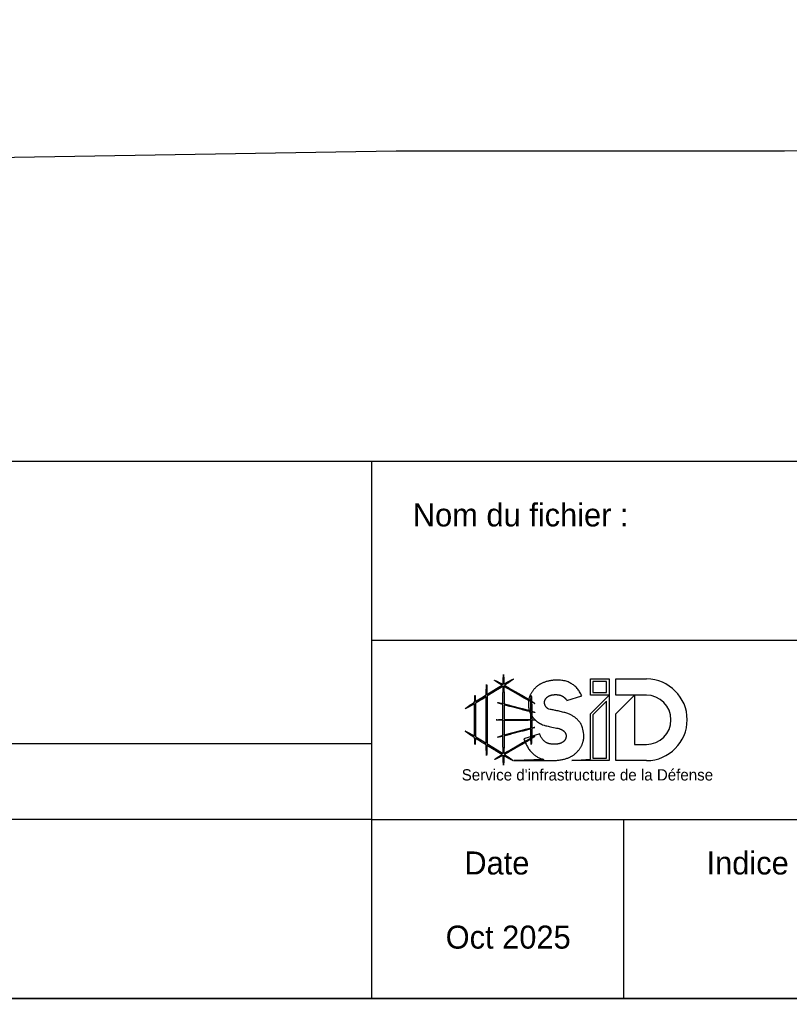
# Model space of a CAD drawing. Extents: x 37864 to 38032, y 453991 to 454052.
# Drawn here: x 38013.02 to 38023.04, y 453990.82 to 454003.57 of the extents above; entities that cross this region are included whole.
import ezdxf

# ---------------------------------------------------------------- set-up
doc = ezdxf.new("R2010")
doc.units = 0
doc.layers.add('PS_Dim', color=7, linetype='Continuous')

msp = doc.modelspace()

# ---------------------------------------------------------------- linework, layer by layer
at = {"layer": 'DEFPOINTS'}
for p, q in [((38017.598, 453997.816), (38017.598, 453990.816)), ((38017.598, 453995.483), (38027.447, 453995.483)), ((38019.104, 453994.778), (38019.226, 453994.853)), ((38019.54, 453994.758), (38019.378, 453994.851)), ((38019.386, 453994.865), (38019.548, 453994.772)), ((38019.033, 453994.734), (38019.094, 453994.772)), ((38019.093, 453994.748), (38019.044, 453994.717)), ((38019.237, 453994.836), (38019.104, 453994.754)), ((38019.312, 453994.657), (38019.312, 453994.716)), ((38019.326, 453994.716), (38019.326, 453994.654)), ((38020.144, 453994.7), (38020.339, 453994.76)), ((38019.092, 453994.303), (38019.092, 453994.588)), ((38019.106, 453994.588), (38019.106, 453994.303)), ((38019.312, 453994.451), (38019.312, 453994.647)), ((38019.326, 453994.643), (38019.326, 453994.451)), ((38019.556, 453994.581), (38019.407, 453994.62)), ((38019.41, 453994.633), (38019.56, 453994.594)), ((38018.941, 453994.347), (38018.941, 453994.544)), ((38018.955, 453994.544), (38018.955, 453994.347)), ((38019.673, 453994.45), (38019.673, 453994.544)), ((38019.687, 453994.544), (38019.687, 453994.449)), ((38019.312, 453994.244), (38019.312, 453994.44)), ((38019.326, 453994.44), (38019.326, 453994.248)), ((38019.398, 453994.452), (38019.552, 453994.452)), ((38019.552, 453994.439), (38019.398, 453994.439)), ((38019.673, 453994.347), (38019.673, 453994.441)), ((38019.687, 453994.442), (38019.687, 453994.347)), ((38019.312, 453994.175), (38019.312, 453994.234)), ((38019.326, 453994.237), (38019.326, 453994.175)), ((38019.407, 453994.271), (38019.556, 453994.31)), ((38019.56, 453994.297), (38019.41, 453994.258)), ((38019.094, 453994.119), (38019.033, 453994.157)), ((38019.044, 453994.174), (38019.093, 453994.143)), ((38019.104, 453994.137), (38019.237, 453994.055)), ((38019.226, 453994.038), (38019.104, 453994.113)), ((38019.378, 453994.04), (38019.54, 453994.133)), ((38019.548, 453994.119), (38019.386, 453994.026)), ((38019.842, 453993.93), (38019.457, 453993.916)), ((38019.457, 453993.916), (38019.968, 453993.916)), ((38017.598, 453993.149), (38032.431, 453993.149)), ((38020.881, 453993.149), (38020.881, 453990.816))]:
    msp.add_line(p, q, dxfattribs=at)
for points in [[(37950.431, 453990.816), (38032.431, 453990.816), (38032.431, 454048.216), (37950.431, 454048.216)], [(37992.431, 453997.816), (38032.431, 453997.816), (38032.431, 453990.816), (37992.431, 453990.816)], [(38020.451, 453994.979), (38020.694, 453994.979), (38020.694, 453994.768), (38020.451, 453994.768)], [(38020.484, 453994.801), (38020.662, 453994.801), (38020.662, 453994.946), (38020.484, 453994.946)], [(38020.694, 453993.916), (38020.451, 453993.916), (38020.209, 453993.916), (38020.451, 453993.936), (38020.451, 453994.525), (38020.694, 453994.768)], [(38020.662, 453994.689), (38020.484, 453994.511), (38020.484, 453993.948), (38020.662, 453993.948)], [(38002.944, 453994.139), (38017.598, 453994.139), (38017.598, 453993.149), (38002.944, 453993.149)]]:
    msp.add_lwpolyline(points, close=True, dxfattribs=at)
for points in [[(38021.179, 453994.768), (38020.783, 453994.768), (38020.783, 453994.979), (38021.183, 453994.979)], [(38021.183, 453993.916), (38020.783, 453993.916), (38020.783, 453994.525), (38021.026, 453994.768), (38021.026, 453994.126), (38021.179, 453994.126)], [(38019.796, 453994.247), (38019.79, 453994.264), (38019.585, 453994.201)]]:
    msp.add_lwpolyline(points, dxfattribs=at)
for radius, start, end in [(0.532, 270.4248, 89.5752), (0.321, 270, 90)]:
    msp.add_arc((38021.179, 453994.447), radius, start, end, dxfattribs=at)
for points, degree in [([(38019.314, 453994.906), (38019.315, 453994.961), (38019.317, 453995.008), (38019.319, 453995.036)], 2), ([(38019.319, 453995.036), (38019.321, 453995.009), (38019.323, 453994.964), (38019.324, 453994.912)], 2), ([(38019.324, 453994.912), (38019.375, 453994.941), (38019.422, 453994.967), (38019.448, 453994.978)], 2), ([(38019.448, 453994.978), (38019.427, 453994.96), (38019.381, 453994.929), (38019.331, 453994.896)], 2), ([(38019.094, 453994.772), (38019.095, 453994.829), (38019.096, 453994.879), (38019.099, 453994.908)], 2), ([(38019.099, 453994.908), (38019.101, 453994.88), (38019.103, 453994.833), (38019.104, 453994.778)], 2), ([(38019.299, 453994.897), (38019.257, 453994.923), (38019.219, 453994.948), (38019.2, 453994.963)], 2), ([(38019.2, 453994.963), (38019.223, 453994.954), (38019.268, 453994.931), (38019.314, 453994.906)], 2), ([(38019.226, 453994.853), (38019.231, 453994.856), (38019.235, 453994.859), (38019.24, 453994.862)], 2), ([(38019.25, 453994.845), (38019.246, 453994.842), (38019.241, 453994.839), (38019.237, 453994.836)], 2), ([(38019.24, 453994.862), (38019.259, 453994.873), (38019.279, 453994.885), (38019.299, 453994.897)], 2), ([(38019.314, 453994.885), (38019.292, 453994.871), (38019.271, 453994.857), (38019.25, 453994.845)], 2), ([(38019.312, 453994.736), (38019.312, 453994.784), (38019.313, 453994.836), (38019.314, 453994.885)], 2), ([(38019.314, 453994.906), (38019.314, 453994.906), (38019.314, 453994.906), (38019.314, 453994.906)], 2), ([(38019.324, 453994.882), (38019.325, 453994.834), (38019.326, 453994.783), (38019.326, 453994.736)], 2), ([(38019.366, 453994.857), (38019.353, 453994.865), (38019.339, 453994.874), (38019.324, 453994.882)], 2), ([(38019.331, 453994.896), (38019.346, 453994.888), (38019.361, 453994.88), (38019.375, 453994.872)], 2), ([(38019.378, 453994.851), (38019.374, 453994.853), (38019.37, 453994.855), (38019.366, 453994.857)], 2), ([(38019.375, 453994.872), (38019.379, 453994.87), (38019.382, 453994.867), (38019.386, 453994.865)], 2), ([(38019.72, 453994.849), (38019.632, 453994.752), (38019.644, 453994.624)], 2), ([(38019.967, 453994.962), (38019.808, 453994.946), (38019.72, 453994.849)], 2), ([(38020.339, 453994.76), (38020.231, 453994.988), (38019.967, 453994.962)], 2), ([(38018.943, 453994.677), (38018.944, 453994.714), (38018.946, 453994.747), (38018.948, 453994.765)], 2), ([(38018.948, 453994.765), (38018.95, 453994.748), (38018.952, 453994.718), (38018.953, 453994.684)], 2), ([(38018.953, 453994.684), (38018.975, 453994.698), (38018.998, 453994.712), (38019.019, 453994.726)], 2), ([(38019.019, 453994.726), (38019.024, 453994.729), (38019.028, 453994.732), (38019.033, 453994.734)], 2), ([(38019.044, 453994.717), (38019.039, 453994.714), (38019.034, 453994.712), (38019.03, 453994.709)], 2), ([(38019.092, 453994.608), (38019.092, 453994.653), (38019.093, 453994.702), (38019.093, 453994.748)], 2), ([(38019.104, 453994.754), (38019.105, 453994.707), (38019.105, 453994.655), (38019.106, 453994.608)], 2), ([(38019.312, 453994.716), (38019.312, 453994.722), (38019.312, 453994.729), (38019.312, 453994.736)], 2), ([(38019.326, 453994.736), (38019.326, 453994.729), (38019.326, 453994.722), (38019.326, 453994.716)], 2), ([(38019.551, 453994.751), (38019.547, 453994.753), (38019.543, 453994.756), (38019.54, 453994.758)], 2), ([(38019.548, 453994.772), (38019.552, 453994.77), (38019.556, 453994.768), (38019.56, 453994.766)], 2), ([(38019.676, 453994.684), (38019.638, 453994.703), (38019.592, 453994.728), (38019.551, 453994.751)], 2), ([(38019.56, 453994.766), (38019.598, 453994.743), (38019.642, 453994.717), (38019.676, 453994.695)], 2), ([(38019.676, 453994.695), (38019.677, 453994.724), (38019.678, 453994.75), (38019.68, 453994.765)], 2), ([(38019.68, 453994.765), (38019.682, 453994.749), (38019.684, 453994.721), (38019.685, 453994.689)], 2), ([(38019.854, 453994.662), (38019.849, 453994.702), (38019.88, 453994.735)], 2), ([(38019.88, 453994.735), (38019.912, 453994.769), (38019.975, 453994.774)], 2), ([(38019.975, 453994.774), (38020.046, 453994.78), (38020.09, 453994.753)], 2), ([(38020.09, 453994.753), (38020.118, 453994.736), (38020.144, 453994.7)], 2), ([(38018.821, 453994.592), (38018.844, 453994.611), (38018.891, 453994.644), (38018.943, 453994.677)], 2), ([(38018.942, 453994.657), (38018.893, 453994.628), (38018.847, 453994.603), (38018.821, 453994.592)], 2), ([(38018.941, 453994.558), (38018.941, 453994.59), (38018.942, 453994.625), (38018.942, 453994.657)], 2), ([(38019.03, 453994.709), (38019.005, 453994.694), (38018.979, 453994.678), (38018.953, 453994.663)], 2), ([(38018.953, 453994.663), (38018.954, 453994.629), (38018.955, 453994.592), (38018.955, 453994.558)], 2), ([(38019.092, 453994.588), (38019.092, 453994.595), (38019.092, 453994.601), (38019.092, 453994.608)], 2), ([(38019.106, 453994.608), (38019.106, 453994.601), (38019.106, 453994.595), (38019.106, 453994.588)], 2), ([(38019.312, 453994.647), (38019.282, 453994.656), (38019.255, 453994.664), (38019.241, 453994.671)], 2), ([(38019.241, 453994.671), (38019.256, 453994.669), (38019.282, 453994.664), (38019.312, 453994.657)], 2), ([(38019.326, 453994.654), (38019.35, 453994.648), (38019.376, 453994.642), (38019.4, 453994.636)], 2), ([(38019.396, 453994.623), (38019.374, 453994.629), (38019.349, 453994.636), (38019.326, 453994.643)], 2), ([(38019.407, 453994.62), (38019.403, 453994.621), (38019.4, 453994.622), (38019.396, 453994.623)], 2), ([(38019.4, 453994.636), (38019.403, 453994.635), (38019.407, 453994.634), (38019.41, 453994.633)], 2), ([(38019.56, 453994.594), (38019.563, 453994.593), (38019.567, 453994.592), (38019.57, 453994.591)], 2), ([(38019.57, 453994.591), (38019.604, 453994.582), (38019.642, 453994.571), (38019.673, 453994.562)], 2), ([(38019.644, 453994.624), (38019.652, 453994.539), (38019.702, 453994.477)], 2), ([(38019.673, 453994.562), (38019.674, 453994.602), (38019.674, 453994.646), (38019.676, 453994.684)], 2), ([(38019.685, 453994.689), (38019.702, 453994.678), (38019.716, 453994.668), (38019.726, 453994.66)], 2), ([(38019.726, 453994.66), (38019.716, 453994.664), (38019.702, 453994.671), (38019.685, 453994.679)], 2), ([(38019.685, 453994.679), (38019.686, 453994.641), (38019.687, 453994.597), (38019.687, 453994.558)], 2), ([(38019.901, 453994.59), (38019.858, 453994.619), (38019.854, 453994.662)], 2), ([(38020.365, 453994.256), (38020.363, 453994.29), (38020.346, 453994.351), (38020.331, 453994.388), (38020.306, 453994.424), (38020.272, 453994.46), (38020.241, 453994.486), (38020.207, 453994.507), (38020.169, 453994.525), (38020.12, 453994.54), (38020.058, 453994.555), (38019.999, 453994.569), (38019.96, 453994.576), (38019.912, 453994.585), (38019.901, 453994.59)], 3), ([(38018.941, 453994.544), (38018.941, 453994.549), (38018.941, 453994.553), (38018.941, 453994.558)], 2), ([(38018.955, 453994.558), (38018.955, 453994.553), (38018.955, 453994.549), (38018.955, 453994.544)], 2), ([(38019.567, 453994.578), (38019.563, 453994.579), (38019.56, 453994.58), (38019.556, 453994.581)], 2), ([(38019.673, 453994.553), (38019.641, 453994.56), (38019.601, 453994.569), (38019.567, 453994.578)], 2), ([(38019.673, 453994.544), (38019.673, 453994.547), (38019.673, 453994.55), (38019.673, 453994.553)], 2), ([(38019.687, 453994.558), (38019.687, 453994.558), (38019.687, 453994.558), (38019.687, 453994.557)], 2), ([(38019.687, 453994.557), (38019.703, 453994.552), (38019.717, 453994.547), (38019.726, 453994.544)], 2), ([(38019.726, 453994.544), (38019.716, 453994.544), (38019.703, 453994.547), (38019.687, 453994.55)], 2), ([(38019.687, 453994.55), (38019.687, 453994.548), (38019.687, 453994.546), (38019.687, 453994.544)], 2), ([(38019.702, 453994.477), (38019.751, 453994.416), (38019.815, 453994.388)], 2), ([(38018.941, 453994.333), (38018.941, 453994.338), (38018.941, 453994.342), (38018.941, 453994.347)], 2), ([(38018.942, 453994.234), (38018.942, 453994.266), (38018.941, 453994.301), (38018.941, 453994.333)], 2), ([(38018.955, 453994.333), (38018.955, 453994.299), (38018.954, 453994.262), (38018.953, 453994.228)], 2), ([(38018.955, 453994.347), (38018.955, 453994.342), (38018.955, 453994.338), (38018.955, 453994.333)], 2), ([(38019.224, 453994.446), (38019.242, 453994.448), (38019.275, 453994.45), (38019.312, 453994.451)], 2), ([(38019.312, 453994.44), (38019.275, 453994.441), (38019.242, 453994.443), (38019.224, 453994.446)], 2), ([(38019.326, 453994.451), (38019.346, 453994.452), (38019.367, 453994.452), (38019.387, 453994.452)], 2), ([(38019.387, 453994.439), (38019.367, 453994.439), (38019.346, 453994.439), (38019.326, 453994.44)], 2), ([(38019.387, 453994.452), (38019.391, 453994.452), (38019.394, 453994.452), (38019.398, 453994.452)], 2), ([(38019.398, 453994.439), (38019.394, 453994.439), (38019.391, 453994.439), (38019.387, 453994.439)], 2), ([(38019.552, 453994.452), (38019.556, 453994.452), (38019.559, 453994.452), (38019.563, 453994.452)], 2), ([(38019.563, 453994.439), (38019.559, 453994.439), (38019.556, 453994.439), (38019.552, 453994.439)], 2), ([(38019.563, 453994.452), (38019.599, 453994.452), (38019.64, 453994.451), (38019.673, 453994.45)], 2), ([(38019.673, 453994.441), (38019.64, 453994.44), (38019.599, 453994.439), (38019.563, 453994.439)], 2), ([(38019.567, 453994.313), (38019.601, 453994.322), (38019.641, 453994.331), (38019.673, 453994.338)], 2), ([(38019.673, 453994.338), (38019.673, 453994.341), (38019.673, 453994.344), (38019.673, 453994.347)], 2), ([(38019.687, 453994.333), (38019.687, 453994.294), (38019.686, 453994.25), (38019.685, 453994.212)], 2), ([(38019.687, 453994.449), (38019.703, 453994.448), (38019.717, 453994.447), (38019.726, 453994.446)], 2), ([(38019.726, 453994.446), (38019.717, 453994.444), (38019.703, 453994.443), (38019.687, 453994.442)], 2), ([(38019.687, 453994.347), (38019.687, 453994.345), (38019.687, 453994.343), (38019.687, 453994.341)], 2), ([(38019.687, 453994.341), (38019.703, 453994.344), (38019.716, 453994.347), (38019.726, 453994.347)], 2), ([(38019.726, 453994.347), (38019.717, 453994.344), (38019.703, 453994.339), (38019.687, 453994.334)], 2), ([(38019.687, 453994.334), (38019.687, 453994.333), (38019.687, 453994.333), (38019.687, 453994.333)], 2), ([(38019.815, 453994.388), (38019.823, 453994.385), (38019.843, 453994.378), (38019.898, 453994.362), (38019.962, 453994.35), (38020.031, 453994.336), (38020.038, 453994.333)], 3), ([(38020.038, 453994.333), (38020.087, 453994.316), (38020.104, 453994.3)], 2), ([(38018.943, 453994.214), (38018.891, 453994.247), (38018.844, 453994.28), (38018.821, 453994.299)], 2), ([(38018.821, 453994.299), (38018.847, 453994.288), (38018.893, 453994.263), (38018.942, 453994.234)], 2), ([(38018.948, 453994.126), (38018.946, 453994.144), (38018.944, 453994.177), (38018.943, 453994.214)], 2), ([(38018.953, 453994.207), (38018.952, 453994.173), (38018.95, 453994.143), (38018.948, 453994.126)], 2), ([(38018.953, 453994.228), (38018.979, 453994.213), (38019.005, 453994.197), (38019.03, 453994.182)], 2), ([(38019.019, 453994.165), (38018.998, 453994.179), (38018.975, 453994.193), (38018.953, 453994.207)], 2), ([(38019.092, 453994.283), (38019.092, 453994.29), (38019.092, 453994.296), (38019.092, 453994.303)], 2), ([(38019.093, 453994.143), (38019.093, 453994.189), (38019.092, 453994.238), (38019.092, 453994.283)], 2), ([(38019.106, 453994.283), (38019.105, 453994.236), (38019.105, 453994.184), (38019.104, 453994.137)], 2), ([(38019.106, 453994.303), (38019.106, 453994.296), (38019.106, 453994.29), (38019.106, 453994.283)], 2), ([(38019.241, 453994.22), (38019.255, 453994.227), (38019.282, 453994.235), (38019.312, 453994.244)], 2), ([(38019.312, 453994.234), (38019.282, 453994.227), (38019.256, 453994.222), (38019.241, 453994.22)], 2), ([(38019.326, 453994.248), (38019.349, 453994.255), (38019.374, 453994.262), (38019.396, 453994.268)], 2), ([(38019.4, 453994.255), (38019.376, 453994.249), (38019.35, 453994.243), (38019.326, 453994.237)], 2), ([(38019.396, 453994.268), (38019.4, 453994.269), (38019.403, 453994.27), (38019.407, 453994.271)], 2), ([(38019.41, 453994.258), (38019.407, 453994.257), (38019.403, 453994.256), (38019.4, 453994.255)], 2), ([(38019.551, 453994.14), (38019.592, 453994.163), (38019.638, 453994.188), (38019.676, 453994.207)], 2), ([(38019.556, 453994.31), (38019.56, 453994.311), (38019.563, 453994.312), (38019.567, 453994.313)], 2), ([(38019.57, 453994.3), (38019.567, 453994.299), (38019.563, 453994.298), (38019.56, 453994.297)], 2), ([(38019.673, 453994.329), (38019.642, 453994.32), (38019.604, 453994.309), (38019.57, 453994.3)], 2), ([(38019.676, 453994.207), (38019.674, 453994.245), (38019.674, 453994.289), (38019.673, 453994.329)], 2), ([(38019.685, 453994.212), (38019.702, 453994.22), (38019.716, 453994.227), (38019.726, 453994.231)], 2), ([(38019.726, 453994.231), (38019.716, 453994.223), (38019.702, 453994.213), (38019.685, 453994.202)], 2), ([(38019.991, 453994.128), (38019.847, 453994.121), (38019.796, 453994.247)], 2), ([(38020.134, 453994.24), (38020.137, 453994.196), (38020.101, 453994.164)], 2), ([(38020.104, 453994.3), (38020.132, 453994.273), (38020.134, 453994.24)], 2), ([(38020.275, 453994.026), (38020.372, 453994.124), (38020.365, 453994.256)], 2), ([(38019.033, 453994.157), (38019.028, 453994.159), (38019.024, 453994.162), (38019.019, 453994.165)], 2), ([(38019.03, 453994.182), (38019.034, 453994.179), (38019.039, 453994.177), (38019.044, 453994.174)], 2), ([(38019.099, 453993.983), (38019.096, 453994.012), (38019.095, 453994.062), (38019.094, 453994.119)], 2), ([(38019.104, 453994.113), (38019.103, 453994.058), (38019.101, 453994.011), (38019.099, 453993.983)], 2), ([(38019.312, 453994.155), (38019.312, 453994.162), (38019.312, 453994.169), (38019.312, 453994.175)], 2), ([(38019.314, 453994.006), (38019.313, 453994.055), (38019.312, 453994.107), (38019.312, 453994.155)], 2), ([(38019.326, 453994.155), (38019.326, 453994.108), (38019.325, 453994.057), (38019.324, 453994.009)], 2), ([(38019.326, 453994.175), (38019.326, 453994.169), (38019.326, 453994.162), (38019.326, 453994.155)], 2), ([(38019.54, 453994.133), (38019.543, 453994.135), (38019.547, 453994.138), (38019.551, 453994.14)], 2), ([(38019.56, 453994.125), (38019.556, 453994.123), (38019.552, 453994.121), (38019.548, 453994.119)], 2), ([(38019.676, 453994.196), (38019.642, 453994.174), (38019.598, 453994.148), (38019.56, 453994.125)], 2), ([(38019.585, 453994.201), (38019.655, 453993.98), (38019.842, 453993.93)], 2), ([(38019.68, 453994.126), (38019.678, 453994.141), (38019.677, 453994.167), (38019.676, 453994.196)], 2), ([(38019.685, 453994.202), (38019.684, 453994.17), (38019.682, 453994.142), (38019.68, 453994.126)], 2), ([(38020.101, 453994.164), (38020.066, 453994.132), (38019.991, 453994.128)], 2), ([(38019.2, 453993.928), (38019.219, 453993.943), (38019.257, 453993.968), (38019.299, 453993.994)], 2), ([(38019.314, 453993.985), (38019.268, 453993.96), (38019.223, 453993.937), (38019.2, 453993.928)], 2), ([(38019.24, 453994.029), (38019.235, 453994.032), (38019.231, 453994.035), (38019.226, 453994.038)], 2), ([(38019.237, 453994.055), (38019.241, 453994.052), (38019.246, 453994.049), (38019.25, 453994.046)], 2), ([(38019.299, 453993.994), (38019.279, 453994.006), (38019.259, 453994.018), (38019.24, 453994.029)], 2), ([(38019.25, 453994.046), (38019.271, 453994.034), (38019.292, 453994.02), (38019.314, 453994.006)], 2), ([(38019.319, 453993.855), (38019.317, 453993.883), (38019.315, 453993.93), (38019.314, 453993.985)], 2), ([(38019.314, 453993.985), (38019.314, 453993.985), (38019.314, 453993.985), (38019.314, 453993.985)], 2), ([(38019.324, 453993.979), (38019.323, 453993.927), (38019.321, 453993.882), (38019.319, 453993.855)], 2), ([(38019.324, 453994.009), (38019.339, 453994.017), (38019.353, 453994.026), (38019.366, 453994.034)], 2), ([(38019.448, 453993.913), (38019.422, 453993.924), (38019.375, 453993.95), (38019.324, 453993.979)], 2), ([(38019.375, 453994.019), (38019.361, 453994.011), (38019.346, 453994.003), (38019.331, 453993.995)], 2), ([(38019.331, 453993.995), (38019.381, 453993.962), (38019.427, 453993.931), (38019.448, 453993.913)], 2), ([(38019.366, 453994.034), (38019.37, 453994.036), (38019.374, 453994.038), (38019.378, 453994.04)], 2), ([(38019.386, 453994.026), (38019.382, 453994.024), (38019.379, 453994.021), (38019.375, 453994.019)], 2), ([(38019.995, 453993.917), (38020.178, 453993.927), (38020.275, 453994.026)], 2), ([(38019.968, 453993.916), (38019.981, 453993.916), (38019.995, 453993.917)], 2)]:
    msp.add_open_spline(points, degree=degree, dxfattribs=at)
at = {"layer": 'PS_Dim'}
msp.add_lwpolyline([(38027.847, 454001.939), (38022.98, 454001.859), (38017.923, 454001.855), (38012.951, 454001.773), (38008.007, 454001.708), (38002.72, 454001.64), (37997.98, 454001.622), (37993.014, 454001.592), (37991.113, 454001.604)], dxfattribs=at)

# ---------------------------------------------------------------- texts
at = {"layer": 'DEFPOINTS'}
for s, height, p in [('Nom du fichier :', 0.3, (38018.138, 453996.967)), ("Service d'infrastructure de la Défense", 0.14709, (38018.775, 453993.656)), ('DUBOIS SANDRINE', 0.0002, (38017.595, 453993.149)), ('DUBOIS SANDRINE', 0.0002, (38017.595, 453993.149)), ('Date', 0.3, (38018.809, 453992.431)), ('Indice', 0.3, (38021.963, 453992.431)), ('Oct 2025', 0.3, (38018.566, 453991.465))]:
    msp.add_text(s, height=height, rotation=360, dxfattribs=at).set_placement(p)

doc.saveas('drawing.dxf')
